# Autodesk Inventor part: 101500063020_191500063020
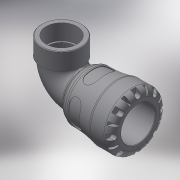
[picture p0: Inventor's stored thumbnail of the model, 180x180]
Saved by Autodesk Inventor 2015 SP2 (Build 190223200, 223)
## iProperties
Created: 2016-12
Part Number: 101500063020_191500063020
Material: Generic
Description: PLASSON 90° ELBOW WITH THREADED FEMALE OFFTAKE 63X2" SERIES 1
Document SubType Name: Modeling
Designer: KIM
Mass: 557.611 g
Surface Area: 990.043 cm^2
Volume: 557.611 cm^3
Density: 1 g/cm^3
Appearance: Default
Author: KIM
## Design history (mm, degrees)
derived "1015.ipt"
feature "Solid1::1015.ipt"
tag "TaggingFeature1"
body "Solid1"
other parameters: "d1" = 37.8, "d2" = 63, "d3" = 78.75, "d4" = 103, "d8" = 90.64, "d13" = 9.7, "d14" = 9.7, "d15" = 0, "d17" = 360 deg, "d19" = 8 deg, "d20" = 1.26, "d21" = 1.26, "d22" = 8 deg, "d24" = 0, "d26" = 360 deg, "d33" = 10.3, "d43" = 84.46, "d51" = 1.03, "d54" = 22.05, "d55" = 13.86, "d57" = 19.012, "d58" = 0, "d74" = 0, "d82" = 1.26, "d115" = 360 deg, "d207" = 90 deg, "d228" = 18.7425, "d247" = 2.06, "d248" = 5.4, "d268" = 49.852, "d269" = 5.4, "d270" = 141, "d281" = 8.4984, "d294" = 56.656, "d295" = 29, "d296" = 31.9, "d297" = 50.9904, "d299" = 66.28752, "d300" = 50.9904, "d301" = 0, "d302" = 0, "d303" = 9.08624, "d306" = 8, "d307" = 9, "d308" = 8, "d310" = 3, "d_" = 63, "E_" = 103, "A_" = 141, "l_2" = 29, "Rp_" = 56.656, "d9" = 12.125, "d11" = 103, "d12" = 78.75, "d298" = 73.6528
